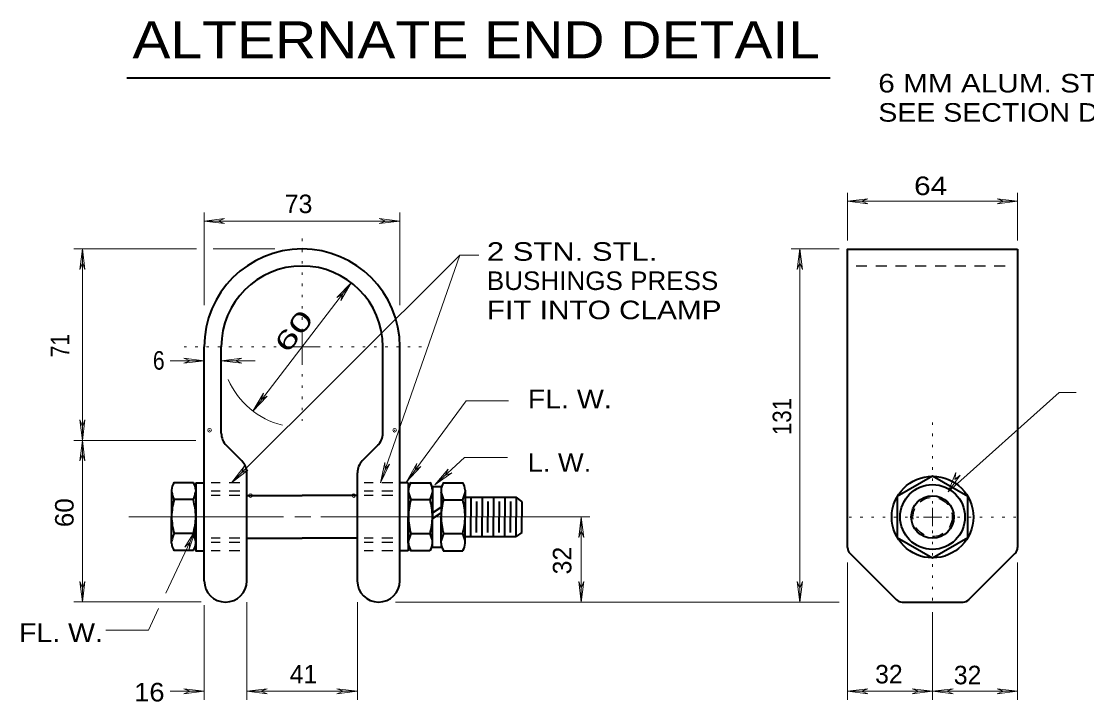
# Model space of a CAD drawing. Extents: x 312583 to 312854, y 144419 to 144597.
# Drawn here: x 312723.53 to 312767.21, y 144463.64 to 144491.52 of the extents above; entities that cross this region are included whole.
import ezdxf

# ---------------------------------------------------------------- set-up
doc = ezdxf.new("R2010")
doc.units = 0
doc.header["$LTSCALE"] = 0.3
doc.header["$PDMODE"] = 32
doc.header["$PDSIZE"] = 0.15
doc.linetypes.add('DOTTED', pattern=[1.5, 0.3, -1.2])
doc.linetypes.add('SHORT_DASHED', pattern=[2.7, 1.5, -1.2])
doc.layers.add('1', color=7, linetype='Continuous', lineweight=13)

msp = doc.modelspace()

# ---------------------------------------------------------------- linework, layer by layer
at = {"layer": '1', "lineweight": 40}
for p, q in [((312727.8533, 144489.2024), (312756.6974, 144489.2024)), ((312764.3764, 144482.182), (312764.3764, 144469.9613)), ((312731.0341, 144468.5966), (312731.0341, 144478.18)), ((312731.7317, 144474.638), (312731.7317, 144478.18)), ((312738.3557, 144474.638), (312738.3557, 144478.18)), ((312739.0534, 144468.5966), (312739.0534, 144478.18)), ((312731.9311, 144474.1473), (312732.5751, 144473.5033)), ((312738.1487, 144474.1473), (312737.5124, 144473.5033)), ((312732.7744, 144468.5966), (312732.7744, 144473.0126)), ((312737.3131, 144468.5966), (312737.3131, 144473.0126)), ((312730.5971, 144472.614), (312729.7997, 144472.614)), ((312730.6891, 144472.6063), (312731.0341, 144472.6063)), ((312739.3984, 144472.6063), (312739.0534, 144472.6063)), ((312739.3984, 144472.6063), (312739.3984, 144469.8156)), ((312739.4904, 144472.614), (312740.2877, 144472.614)), ((312740.8321, 144472.614), (312741.6294, 144472.614)), ((312729.6924, 144472.3073), (312729.6924, 144471.2033)), ((312730.6891, 144472.315), (312730.6891, 144471.211)), ((312732.7744, 144472.085), (312735.0437, 144472.085)), ((312737.3131, 144472.085), (312735.0437, 144472.085)), ((312739.3984, 144472.315), (312739.3984, 144471.211)), ((312740.3874, 144472.453), (312740.7401, 144472.453)), ((312740.3874, 144472.453), (312740.3874, 144472.3073)), ((312740.3874, 144472.3073), (312740.3874, 144471.2033)), ((312740.7401, 144472.453), (312740.7401, 144472.3073)), ((312740.7401, 144472.3073), (312740.7401, 144471.2033)), ((312741.7291, 144472.3073), (312741.7291, 144471.2033)), ((312730.5894, 144471.924), (312729.7921, 144471.924)), ((312739.4981, 144471.924), (312740.2954, 144471.924)), ((312740.8321, 144471.9163), (312741.6294, 144471.9163)), ((312741.9591, 144472.016), (312741.9591, 144471.2033)), ((312742.1967, 144471.8473), (312742.1967, 144471.2033)), ((312742.4267, 144472.016), (312742.4267, 144471.2033)), ((312742.6567, 144471.8473), (312742.6567, 144471.2033)), ((312742.8944, 144472.016), (312742.8944, 144471.2033)), ((312743.1244, 144471.8473), (312743.1244, 144471.2033)), ((312743.3544, 144472.016), (312743.3544, 144471.2033)), ((312743.5844, 144471.8473), (312743.5844, 144471.2033)), ((312744.0521, 144471.8473), (312743.8221, 144472.016)), ((312744.0521, 144471.8473), (312744.0521, 144471.2033)), ((312729.6924, 144470.1376), (312729.6924, 144471.2186)), ((312730.6891, 144470.13), (312730.6891, 144471.211)), ((312739.3984, 144470.13), (312739.3984, 144471.211)), ((312740.3874, 144471.3796), (312740.7401, 144471.6096)), ((312740.3874, 144471.1496), (312740.7401, 144471.3796)), ((312740.3874, 144470.1376), (312740.3874, 144471.2186)), ((312740.7401, 144470.13), (312740.7401, 144471.2033)), ((312741.7291, 144470.1376), (312741.7291, 144471.211)), ((312741.9591, 144470.406), (312741.9591, 144471.2186)), ((312742.1967, 144470.5746), (312742.1967, 144471.2186)), ((312742.4267, 144470.406), (312742.4267, 144471.2186)), ((312742.6567, 144470.5746), (312742.6567, 144471.2186)), ((312742.8944, 144470.406), (312742.8944, 144471.2186)), ((312743.1244, 144470.5746), (312743.1244, 144471.2186)), ((312743.3544, 144470.406), (312743.3544, 144471.2186)), ((312743.5844, 144470.5746), (312743.5844, 144471.2186)), ((312743.8221, 144470.406), (312743.8221, 144471.2186)), ((312744.0521, 144470.5746), (312744.0521, 144471.2186)), ((312730.5971, 144470.5363), (312729.7997, 144470.5363)), ((312732.7744, 144470.337), (312735.0437, 144470.337)), ((312737.3131, 144470.337), (312735.0437, 144470.337)), ((312739.4904, 144470.5363), (312740.2877, 144470.5363)), ((312740.8321, 144470.5286), (312741.6294, 144470.5286)), ((312741.7291, 144470.406), (312743.8221, 144470.406)), ((312744.0521, 144470.5746), (312743.8221, 144470.406)), ((312740.3874, 144469.969), (312740.3874, 144470.1376)), ((312740.3874, 144469.969), (312740.7401, 144469.969)), ((312740.7401, 144470.13), (312740.7401, 144469.969)), ((312730.5971, 144469.831), (312729.7997, 144469.831)), ((312739.3984, 144469.8156), (312739.0534, 144469.8156)), ((312739.4904, 144469.831), (312740.2877, 144469.831)), ((312740.8321, 144469.8233), (312741.6294, 144469.8233)), ((312757.5071, 144469.7083), (312759.3931, 144467.8223)), ((312764.2691, 144469.7083), (312762.3831, 144467.8223)), ((312759.6384, 144467.7226), (312762.1377, 144467.7226))]:
    msp.add_line(p, q, dxfattribs=at)
at = {"layer": '1'}
for p, q in [((312757.4074, 144484.4896), (312757.4074, 144482.5346)), ((312764.3764, 144484.4896), (312764.3764, 144482.5346)), ((312757.4074, 144484.1446), (312758.2431, 144484.2443)), ((312757.4074, 144484.1446), (312764.3764, 144484.1446)), ((312757.4074, 144484.1446), (312758.2431, 144484.0373)), ((312758.2431, 144484.2443), (312757.9824, 144484.1446)), ((312758.2431, 144484.0373), (312757.9824, 144484.1446)), ((312763.5407, 144484.2443), (312763.8091, 144484.1446)), ((312764.3764, 144484.1446), (312763.5407, 144484.2443)), ((312763.5407, 144484.0373), (312763.8091, 144484.1446)), ((312764.3764, 144484.1446), (312763.5407, 144484.0373)), ((312731.0341, 144479.8896), (312731.0341, 144483.6846)), ((312731.0341, 144483.332), (312731.8697, 144483.4393)), ((312731.8697, 144483.4393), (312731.6091, 144483.332)), ((312738.2101, 144483.4393), (312738.4784, 144483.332)), ((312739.0457, 144483.332), (312738.2101, 144483.4393)), ((312739.0457, 144479.8896), (312739.0457, 144483.6846)), ((312731.0341, 144483.332), (312739.0457, 144483.332)), ((312731.0341, 144483.332), (312731.8697, 144483.2323)), ((312731.8697, 144483.2323), (312731.6091, 144483.332)), ((312738.2101, 144483.2323), (312738.4784, 144483.332)), ((312739.0457, 144483.332), (312738.2101, 144483.2323)), ((312730.7121, 144482.1896), (312725.6904, 144482.1896)), ((312726.0354, 144482.1896), (312725.9357, 144481.3463)), ((312726.0354, 144482.1896), (312726.1351, 144481.3463)), ((312733.9244, 144482.1896), (312731.3944, 144482.1896)), ((312755.0997, 144482.1896), (312757.0547, 144482.1896)), ((312755.4447, 144482.1896), (312755.3451, 144481.3463)), ((312755.4447, 144482.1896), (312755.4447, 144467.7226)), ((312755.4447, 144482.1896), (312755.5521, 144481.3463)), ((312732.1534, 144472.614), (312741.5067, 144481.929)), ((312738.2561, 144472.614), (312741.5067, 144481.929)), ((312741.5067, 144481.929), (312742.2964, 144481.929)), ((312725.9357, 144481.3463), (312726.0354, 144481.6146)), ((312726.1351, 144481.3463), (312726.0354, 144481.6146)), ((312755.3451, 144481.3463), (312755.4447, 144481.6146)), ((312755.5521, 144481.3463), (312755.4447, 144481.6146)), ((312733.0274, 144475.5503), (312737.0601, 144480.802)), ((312737.0601, 144480.802), (312736.4697, 144480.204)), ((312737.0601, 144480.802), (312736.6307, 144480.0736)), ((312736.4697, 144480.204), (312736.7151, 144480.3496)), ((312736.6307, 144480.0736), (312736.7151, 144480.3496)), ((312735.0437, 144478.18), (312735.0437, 144478.9236)), ((312735.0437, 144478.18), (312734.3001, 144478.18)), ((312735.0437, 144478.18), (312735.0437, 144477.4363)), ((312735.0437, 144478.18), (312735.7874, 144478.18)), ((312731.0341, 144477.6126), (312729.6387, 144477.6126)), ((312730.1984, 144477.72), (312730.4591, 144477.6126)), ((312731.0341, 144477.6126), (312730.1984, 144477.72)), ((312730.1984, 144477.513), (312730.4591, 144477.6126)), ((312731.0341, 144477.6126), (312730.1984, 144477.513)), ((312731.7317, 144477.6126), (312732.5674, 144477.72)), ((312731.7317, 144477.6126), (312732.5674, 144477.513)), ((312733.1271, 144477.6126), (312731.7317, 144477.6126)), ((312732.5674, 144477.72), (312732.2991, 144477.6126)), ((312732.5674, 144477.513), (312732.2991, 144477.6126)), ((312733.0274, 144475.5503), (312733.4567, 144476.2863)), ((312733.0274, 144475.5503), (312733.6177, 144476.156)), ((312733.4567, 144476.2863), (312733.3724, 144476.0103)), ((312733.6177, 144476.156), (312733.3724, 144476.0103)), ((312761.5244, 144472.2383), (312766.0769, 144476.3087)), ((312766.0769, 144476.3087), (312766.7745, 144476.3087)), ((312741.7674, 144475.972), (312739.3294, 144472.6523)), ((312741.7674, 144475.972), (312743.5077, 144475.972)), ((312725.9357, 144475.19), (312726.0354, 144474.9216)), ((312726.0354, 144474.3466), (312725.9357, 144475.19)), ((312726.1351, 144475.19), (312726.0354, 144474.9216)), ((312726.0354, 144474.3466), (312726.1351, 144475.19)), ((312730.6891, 144474.3466), (312725.6904, 144474.3466)), ((312726.0354, 144474.3466), (312725.9357, 144473.511)), ((312726.0354, 144474.3466), (312726.1351, 144473.511)), ((312725.9357, 144473.511), (312726.0354, 144473.7793)), ((312726.1351, 144473.511), (312726.0354, 144473.7793)), ((312738.2561, 144472.614), (312738.4324, 144473.442)), ((312738.2561, 144472.614), (312738.6317, 144473.373)), ((312738.4324, 144473.442), (312738.4477, 144473.1506)), ((312738.6317, 144473.373), (312738.4477, 144473.1506)), ((312739.3294, 144472.6523), (312739.7434, 144473.396)), ((312739.7434, 144473.396), (312739.6667, 144473.1123)), ((312741.6984, 144473.649), (312740.4871, 144472.522)), ((312741.6984, 144473.649), (312743.4617, 144473.649)), ((312732.1534, 144472.614), (312732.6747, 144473.281)), ((312732.1534, 144472.614), (312732.8204, 144473.1276)), ((312732.6747, 144473.281), (312732.5597, 144473.0126)), ((312732.8204, 144473.1276), (312732.5597, 144473.0126)), ((312739.3294, 144472.6523), (312739.9121, 144473.2733)), ((312739.9121, 144473.2733), (312739.6667, 144473.1123)), ((312740.4871, 144472.522), (312741.0314, 144473.1736)), ((312740.4871, 144472.522), (312741.1771, 144473.0203)), ((312741.0314, 144473.1736), (312740.9087, 144472.913)), ((312741.1771, 144473.0203), (312740.9087, 144472.913)), ((312761.5244, 144472.2383), (312761.8387, 144473.028)), ((312761.5244, 144472.2383), (312762.0227, 144472.9283)), ((312761.8387, 144473.028), (312761.8004, 144472.7443)), ((312762.0227, 144472.9283), (312761.8004, 144472.7443)), ((312734.2771, 144471.211), (312727.9444, 144471.211)), ((312735.3964, 144471.211), (312734.7524, 144471.211)), ((312735.8104, 144471.211), (312746.8351, 144471.211)), ((312746.4901, 144471.2033), (312746.3904, 144470.3676)), ((312746.4901, 144467.7226), (312746.4901, 144471.2033)), ((312746.4901, 144471.2033), (312746.5897, 144470.3676)), ((312760.8881, 144471.2033), (312760.5124, 144471.2033)), ((312760.8881, 144471.2033), (312760.8881, 144471.579)), ((312760.8881, 144471.2033), (312761.2637, 144471.2033)), ((312760.8881, 144471.2033), (312760.8881, 144470.8353)), ((312729.4547, 144468.083), (312730.6891, 144470.6896)), ((312730.6891, 144470.6896), (312730.2367, 144469.9766)), ((312730.6891, 144470.6896), (312730.4207, 144469.8846)), ((312746.3904, 144470.3676), (312746.4901, 144470.636)), ((312746.5897, 144470.3676), (312746.4901, 144470.636)), ((312730.2367, 144469.9766), (312730.4437, 144470.1683)), ((312730.4207, 144469.8846), (312730.4437, 144470.1683)), ((312757.4074, 144469.348), (312757.4074, 144463.7206)), ((312764.3764, 144469.348), (312764.3764, 144463.7206)), ((312725.9357, 144468.566), (312726.0354, 144468.2976)), ((312726.0354, 144467.7303), (312725.9357, 144468.566)), ((312726.1351, 144468.566), (312726.0354, 144468.2976)), ((312726.0354, 144467.7303), (312726.1351, 144468.566)), ((312746.3904, 144468.5583), (312746.4901, 144468.29)), ((312746.4901, 144467.7226), (312746.3904, 144468.5583)), ((312746.5897, 144468.5583), (312746.4901, 144468.29)), ((312746.4901, 144467.7226), (312746.5897, 144468.5583)), ((312755.3451, 144468.5583), (312755.4447, 144468.29)), ((312755.4447, 144467.7226), (312755.3451, 144468.5583)), ((312755.5521, 144468.5583), (312755.4447, 144468.29)), ((312755.4447, 144467.7226), (312755.5521, 144468.5583)), ((312730.9037, 144467.7303), (312725.6904, 144467.7303)), ((312732.7744, 144463.7206), (312732.7744, 144467.7226)), ((312737.3131, 144463.7206), (312737.3131, 144467.7226)), ((312738.8771, 144467.7226), (312757.0547, 144467.7226)), ((312728.7417, 144466.5726), (312729.1634, 144467.4543)), ((312731.0341, 144463.7206), (312731.0341, 144467.6)), ((312760.8881, 144467.3086), (312760.8881, 144463.7206)), ((312727.0014, 144466.5726), (312728.7417, 144466.5726)), ((312731.0341, 144464.0656), (312729.6387, 144464.0656)), ((312730.1984, 144464.173), (312730.4591, 144464.0656)), ((312731.0341, 144464.0656), (312730.1984, 144464.173)), ((312730.1984, 144463.966), (312730.4591, 144464.0656)), ((312731.0341, 144464.0656), (312730.1984, 144463.966)), ((312732.7744, 144464.0656), (312733.6177, 144464.173)), ((312732.7744, 144464.0656), (312737.3131, 144464.0656)), ((312732.7744, 144464.0656), (312733.6177, 144463.966)), ((312733.6177, 144464.173), (312733.3494, 144464.0656)), ((312733.6177, 144463.966), (312733.3494, 144464.0656)), ((312736.4697, 144464.173), (312736.7381, 144464.0656)), ((312737.3131, 144464.0656), (312736.4697, 144464.173)), ((312736.4697, 144463.966), (312736.7381, 144464.0656)), ((312737.3131, 144464.0656), (312736.4697, 144463.966)), ((312757.4074, 144464.0656), (312758.2431, 144464.173)), ((312757.4074, 144464.0656), (312760.8881, 144464.0656)), ((312757.4074, 144464.0656), (312758.2431, 144463.966)), ((312758.2431, 144464.173), (312757.9747, 144464.0656)), ((312758.2431, 144463.966), (312757.9747, 144464.0656)), ((312760.0524, 144464.173), (312760.3207, 144464.0656)), ((312760.8881, 144464.0656), (312760.0524, 144464.173)), ((312760.0524, 144463.966), (312760.3207, 144464.0656)), ((312760.8881, 144464.0656), (312760.0524, 144463.966)), ((312760.8881, 144464.0656), (312761.7314, 144464.173)), ((312764.3764, 144464.0656), (312760.8881, 144464.0656)), ((312760.8881, 144464.0656), (312761.7314, 144463.966)), ((312761.7314, 144464.173), (312761.4631, 144464.0656)), ((312761.7314, 144463.966), (312761.4631, 144464.0656)), ((312763.5331, 144464.173), (312763.8014, 144464.0656)), ((312764.3764, 144464.0656), (312763.5331, 144464.173)), ((312763.5331, 144463.966), (312763.8014, 144464.0656)), ((312764.3764, 144464.0656), (312763.5331, 144463.966))]:
    msp.add_line(p, q, dxfattribs=at)
at = {"layer": '1', "linetype": 'DOTTED'}
for p, q in [((312735.0437, 144479.2916), (312735.0437, 144482.849)), ((312733.9857, 144478.18), (312730.0144, 144478.18)), ((312736.1554, 144478.18), (312739.9427, 144478.18)), ((312735.0437, 144477.0606), (312735.0437, 144475.1516)), ((312760.8881, 144471.763), (312760.8881, 144475.1056)), ((312760.3284, 144471.2033), (312757.2464, 144471.2033)), ((312761.4477, 144471.2033), (312764.5451, 144471.2033)), ((312760.8881, 144470.6513), (312760.8881, 144467.5463))]:
    msp.add_line(p, q, dxfattribs=at)
at = {"layer": '1', "linetype": 'SHORT_DASHED', "lineweight": 25}
for p, q in [((312757.7524, 144481.492), (312764.2001, 144481.492)), ((312732.4984, 144472.6063), (312731.3101, 144472.6063)), ((312738.7697, 144472.6063), (312737.5891, 144472.6063)), ((312732.4984, 144472.2613), (312731.3101, 144472.2613)), ((312732.4984, 144472.085), (312731.3101, 144472.085)), ((312738.7697, 144472.2613), (312737.5891, 144472.2613)), ((312738.7697, 144472.085), (312737.5891, 144472.085)), ((312732.4984, 144470.337), (312731.3101, 144470.337)), ((312738.7697, 144470.337), (312737.5891, 144470.337)), ((312732.4984, 144470.1606), (312731.3101, 144470.1606)), ((312738.7697, 144470.1606), (312737.5891, 144470.1606)), ((312732.4984, 144469.8156), (312731.3101, 144469.8156)), ((312738.7697, 144469.8156), (312737.5891, 144469.8156))]:
    msp.add_line(p, q, dxfattribs=at)
at = {"layer": '1'}
msp.add_lwpolyline([(312726.0354, 144467.7303), (312726.0354, 144474.3466), (312726.0354, 144482.1896)], dxfattribs=at)
at = {"layer": '1', "lineweight": 40}
for points in [[(312757.4074, 144469.9613), (312757.4074, 144482.182), (312764.3764, 144482.182)], [(312730.6891, 144472.6063), (312730.6891, 144469.8156), (312731.0341, 144469.8156)], [(312741.7291, 144472.016), (312743.8221, 144472.016), (312743.8221, 144471.2033)]]:
    msp.add_lwpolyline(points, dxfattribs=at)
msp.add_lwpolyline([(312760.8881, 144472.8823), (312759.4391, 144472.0466), (312759.4391, 144470.3676), (312760.8881, 144469.532), (312762.3371, 144470.3676), (312762.3371, 144472.0466)], close=True, dxfattribs=at)
for radius in [1.6727, 1.3279, 0.8712]:
    msp.add_circle((312760.8895, 144471.2068), radius, dxfattribs=at)
at = {"layer": '1', "linetype": 'SHORT_DASHED', "lineweight": 25}
msp.add_circle((312760.8895, 144471.2068), 0.8034, dxfattribs=at)
at = {"layer": '1', "lineweight": 40}
for centre, radius, start, end in [((312735.043, 144478.1793), 4.009, 90, 180), ((312735.043, 144478.1793), 4.009, 0, 90), ((312735.043, 144478.1793), 3.312, 90, 180), ((312735.043, 144478.1793), 3.312, 0, 90), ((312732.428, 144474.6374), 0.697, 180, 225), ((312737.6581, 144474.6374), 0.697, 315, 0), ((312732.0795, 144473.0146), 0.697, 0, 45), ((312738.0066, 144473.0146), 0.697, 135, 180), ((312730.2688, 144472.295), 0.574, 145.8703, 178.33743), ((312730.1107, 144472.295), 0.574, 1.66257, 34.1297), ((312739.9754, 144472.295), 0.574, 145.8703, 178.33743), ((312739.8173, 144472.295), 0.574, 1.66257, 34.1297), ((312741.3136, 144472.2922), 0.574, 145.8703, 178.33743), ((312741.1554, 144472.2922), 0.574, 1.66257, 34.1297), ((312731.3026, 144472.5721), 1.6437, 191.77014, 203.36365), ((312729.0769, 144472.5721), 1.6437, 336.63635, 348.22986), ((312741.0092, 144472.5721), 1.6437, 191.77014, 203.36365), ((312738.7835, 144472.5721), 1.6437, 336.63635, 348.22986), ((312742.3474, 144472.5694), 1.6437, 191.77014, 203.36365), ((312740.1217, 144472.5694), 1.6437, 336.63635, 348.22986), ((312732.6589, 144471.1525), 2.9664, 164.99798, 178.595), ((312727.7205, 144471.1525), 2.9664, 1.405, 15.00202), ((312742.3655, 144471.1525), 2.9664, 164.99798, 178.595), ((312737.4271, 144471.1525), 2.9664, 1.405, 15.00202), ((312743.7037, 144471.1497), 2.9664, 164.99798, 178.595), ((312738.7653, 144471.1497), 2.9664, 1.405, 15.00202), ((312732.6589, 144471.2979), 2.9664, 181.405, 195.00202), ((312727.7205, 144471.2979), 2.9664, 344.99798, 358.595), ((312742.3655, 144471.2979), 2.9664, 181.405, 195.00202), ((312737.4271, 144471.2979), 2.9664, 344.99798, 358.595), ((312743.7037, 144471.2951), 2.9664, 181.405, 195.00202), ((312738.7653, 144471.2951), 2.9664, 344.99798, 358.595), ((312731.3026, 144469.8782), 1.6437, 156.63635, 168.22986), ((312729.0769, 144469.8782), 1.6437, 11.77014, 23.36365), ((312741.0092, 144469.8782), 1.6437, 156.63635, 168.22986), ((312738.7835, 144469.8782), 1.6437, 11.77014, 23.36365), ((312742.3474, 144469.8754), 1.6437, 156.63635, 168.22986), ((312740.1217, 144469.8754), 1.6437, 11.77014, 23.36365), ((312730.2688, 144470.1554), 0.574, 181.66257, 214.1297), ((312730.1107, 144470.1554), 0.574, 325.8703, 358.33743), ((312739.9754, 144470.1554), 0.574, 181.66257, 214.1297), ((312739.8173, 144470.1554), 0.574, 325.8703, 358.33743), ((312741.3136, 144470.1526), 0.574, 181.66257, 214.1297), ((312741.1554, 144470.1526), 0.574, 325.8703, 358.33743), ((312757.7531, 144469.9572), 0.3485, 180, 225), ((312764.0258, 144469.9572), 0.3485, 315, 0), ((312731.9067, 144468.5945), 0.8726, 180, 0), ((312738.1794, 144468.5945), 0.8726, 180, 0), ((312759.6399, 144468.0704), 0.3485, 225, 270), ((312762.1391, 144468.0704), 0.3485, 270, 315)]:
    msp.add_arc(centre, radius, start, end, dxfattribs=at)
at = {"layer": '1'}
msp.add_arc((312735.043, 144478.1793), 3.312, 203.83874, 255.87017, dxfattribs=at)
for p in [(312731.2487, 144474.7606), (312738.8387, 144474.7606), (312732.9277, 144472.085), (312737.1597, 144472.085)]:
    msp.add_point(p, dxfattribs=at)

# ---------------------------------------------------------------- texts
for s, height, width, p in [('ALTERNATE END DETAIL', 1.52, 1.15, (312728.0892, 144489.9962)), ('6 MM ALUM. STIFFENER', 0.76, 1.2, (312758.665, 144488.6006)), ('SEE SECTION D-D', 0.76, 1.15, (312758.665, 144487.4036)), ('64 ', 0.76, 1.2, (312760.133, 144484.3967)), ('2 STN. STL. ', 0.76, 1.25, (312742.6184, 144481.7056)), ('BUSHINGS PRESS', 0.76, 1.05, (312742.6184, 144480.5086)), ('FIT INTO CLAMP', 0.76, 1.2, (312742.6184, 144479.3116)), ('6', 0.76, 0.85, (312728.9282, 144477.2436)), ('FL. W.', 0.76, 1.15, (312744.2983, 144475.661)), ('L. W.', 0.76, 1.1, (312744.2898, 144473.0601)), ('FL. W.', 0.76, 1.15, (312723.4377, 144466.0892)), ('16 ', 0.76, 1.1, (312728.1614, 144463.6517))]:
    msp.add_text(s, height=height, dxfattribs=dict(at, width=width)).set_placement(p)
for s, p in [('73', (312734.3349, 144483.6568)), ('41 ', (312734.5385, 144464.3905)), ('32', (312758.5354, 144464.3886)), ('32', (312761.7611, 144464.3532))]:
    msp.add_text(s, height=0.76, dxfattribs=at).set_placement(p)
for s, rotation, width, p in [('60', 52.455, 1.6, (312734.4561, 144477.8761)), ('71', 90, 0.85, (312725.5002, 144477.7491)), ('131', 90, 0.9, (312755.0944, 144474.5614)), ('60', 90, 1.05, (312725.6774, 144470.791))]:
    msp.add_text(s, height=0.76, rotation=rotation, dxfattribs=dict(at, width=width)).set_placement(p)
msp.add_text('32', height=0.76, rotation=90, dxfattribs=at).set_placement((312746.0838, 144468.856))

doc.saveas('drawing.dxf')
